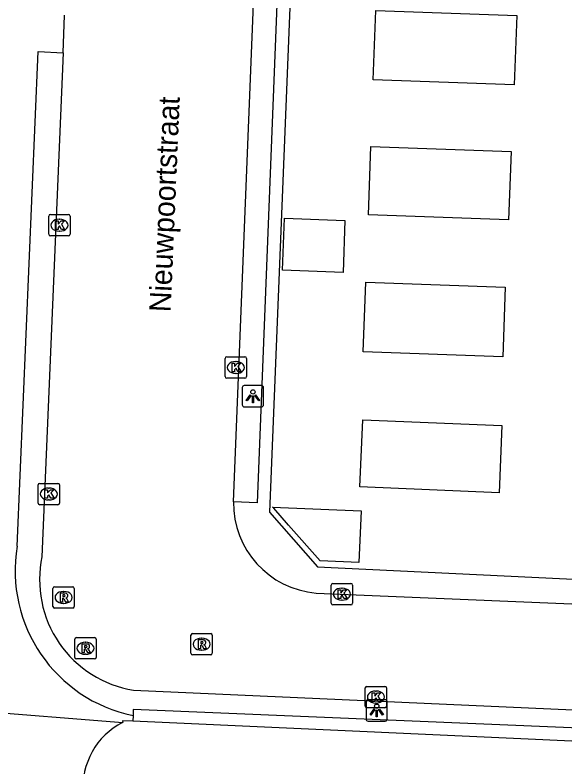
# Model space of a CAD drawing. Extents: x 160732 to 162105, y 387428 to 388479.
# Drawn here: x 161104.81 to 161130.59, y 387524.95 to 387560.21 of the extents above; entities that cross this region are included whole.
import ezdxf

# ---------------------------------------------------------------- set-up
doc = ezdxf.new("R2010")
doc.units = 0
for name, color, linetype in [('IMGEO_Kolk', 7, 'Continuous'), ('IMGEO_Lichtpunt', 7, 'Continuous'), ('IMGEO_Openbare_ruimte_label', 7, 'Continuous'), ('IMGEO_Pand', 7, 'Continuous'), ('IMGEO_Rijbaan_lokaal_open', 7, 'Continuous'), ('IMGEO_Rioolput', 7, 'Continuous'), ('IMGEO_Voetpad_open', 7, 'Continuous')]:
    doc.layers.add(name, color=color, linetype=linetype)

msp = doc.modelspace()

# ---------------------------------------------------------------- linework, layer by layer
at = {"layer": 'IMGEO_Kolk'}
for p, q in [((161106.393, 387549.931), (161106.393, 387550.783)), ((161106.468, 387550.857), (161107.32, 387550.857)), ((161106.881, 387550.637), (161106.906, 387550.637)), ((161107.394, 387550.783), (161107.394, 387549.931)), ((161106.904, 387550.077), (161106.879, 387550.077)), ((161107.32, 387549.857), (161106.468, 387549.857)), ((161114.664, 387543.255), (161114.664, 387544.107)), ((161114.739, 387544.181), (161115.591, 387544.181)), ((161115.152, 387543.961), (161115.177, 387543.961)), ((161115.665, 387544.107), (161115.665, 387543.255)), ((161115.175, 387543.401), (161115.15, 387543.401)), ((161115.591, 387543.181), (161114.739, 387543.181)), ((161105.895, 387537.323), (161105.895, 387538.175)), ((161105.97, 387538.249), (161106.822, 387538.249)), ((161106.383, 387538.029), (161106.408, 387538.029)), ((161106.896, 387538.175), (161106.896, 387537.323)), ((161106.822, 387537.249), (161105.97, 387537.249)), ((161106.406, 387537.469), (161106.381, 387537.469)), ((161119.636, 387532.626), (161119.636, 387533.478)), ((161119.711, 387533.552), (161120.563, 387533.552)), ((161120.124, 387533.332), (161120.149, 387533.332)), ((161120.637, 387533.478), (161120.637, 387532.626)), ((161120.147, 387532.772), (161120.122, 387532.772)), ((161120.563, 387532.552), (161119.711, 387532.552)), ((161121.23, 387527.8), (161121.23, 387528.652)), ((161121.305, 387528.726), (161122.157, 387528.726)), ((161121.718, 387528.506), (161121.743, 387528.506)), ((161122.231, 387528.652), (161122.231, 387527.8)), ((161122.157, 387527.726), (161121.305, 387527.726)), ((161121.741, 387527.946), (161121.716, 387527.946))]:
    msp.add_line(p, q, dxfattribs=at)
for points in [[(161106.393, 387549.931), (161106.393, 387550.783)], [(161106.468, 387550.857), (161107.32, 387550.857)], [(161107.394, 387550.783), (161107.394, 387549.931)], [(161106.714, 387550.557), (161106.837, 387550.557), (161106.837, 387550.406), (161106.967, 387550.557), (161107.131, 387550.557), (161106.985, 387550.406), (161107.138, 387550.157), (161106.986, 387550.157), (161106.901, 387550.321), (161106.837, 387550.254), (161106.837, 387550.157), (161106.714, 387550.157), (161106.714, 387550.557)], [(161107.32, 387549.857), (161106.468, 387549.857)], [(161114.664, 387543.255), (161114.664, 387544.107)], [(161114.739, 387544.181), (161115.591, 387544.181)], [(161115.665, 387544.107), (161115.665, 387543.255)], [(161114.985, 387543.881), (161115.108, 387543.881), (161115.108, 387543.73), (161115.238, 387543.881), (161115.402, 387543.881), (161115.256, 387543.73), (161115.409, 387543.481), (161115.257, 387543.481), (161115.172, 387543.645), (161115.108, 387543.578), (161115.108, 387543.481), (161114.985, 387543.481), (161114.985, 387543.881)], [(161115.591, 387543.181), (161114.739, 387543.181)], [(161105.895, 387537.323), (161105.895, 387538.175)], [(161105.97, 387538.249), (161106.822, 387538.249)], [(161106.216, 387537.949), (161106.339, 387537.949), (161106.339, 387537.798), (161106.469, 387537.949), (161106.633, 387537.949), (161106.487, 387537.798), (161106.64, 387537.549), (161106.488, 387537.549), (161106.403, 387537.713), (161106.339, 387537.646), (161106.339, 387537.549), (161106.216, 387537.549), (161106.216, 387537.949)], [(161106.896, 387538.175), (161106.896, 387537.323)], [(161106.822, 387537.249), (161105.97, 387537.249)], [(161119.636, 387532.626), (161119.636, 387533.478)], [(161119.711, 387533.552), (161120.563, 387533.552)], [(161120.637, 387533.478), (161120.637, 387532.626)], [(161119.957, 387533.252), (161120.08, 387533.252), (161120.08, 387533.101), (161120.21, 387533.252), (161120.374, 387533.252), (161120.228, 387533.101), (161120.381, 387532.852), (161120.229, 387532.852), (161120.144, 387533.016), (161120.08, 387532.949), (161120.08, 387532.852), (161119.957, 387532.852), (161119.957, 387533.252)], [(161120.563, 387532.552), (161119.711, 387532.552)], [(161121.23, 387527.8), (161121.23, 387528.652)], [(161121.305, 387528.726), (161122.157, 387528.726)], [(161121.551, 387528.426), (161121.674, 387528.426), (161121.674, 387528.275), (161121.804, 387528.426), (161121.968, 387528.426), (161121.822, 387528.275), (161121.975, 387528.026), (161121.823, 387528.026), (161121.738, 387528.19), (161121.674, 387528.123), (161121.674, 387528.026), (161121.551, 387528.026), (161121.551, 387528.426)], [(161122.231, 387528.652), (161122.231, 387527.8)], [(161122.157, 387527.726), (161121.305, 387527.726)]]:
    msp.add_lwpolyline(points, dxfattribs=at)
for centre, start, end in [((161106.47, 387550.781), 91.552, 178.448), ((161106.47, 387550.781), 91.552, 178.448), ((161107.318, 387550.781), 1.552, 88.448), ((161107.318, 387550.781), 1.552, 88.448), ((161106.47, 387549.933), 181.552, 268.448), ((161106.47, 387549.933), 181.552, 268.448), ((161107.318, 387549.933), 271.552, 358.448), ((161107.318, 387549.933), 271.552, 358.448), ((161114.741, 387544.105), 91.552, 178.448), ((161114.741, 387544.105), 91.552, 178.448), ((161115.589, 387544.105), 1.552, 88.448), ((161115.589, 387544.105), 1.552, 88.448), ((161114.741, 387543.257), 181.552, 268.448), ((161114.741, 387543.257), 181.552, 268.448), ((161115.589, 387543.257), 271.552, 358.448), ((161115.589, 387543.257), 271.552, 358.448), ((161105.972, 387538.173), 91.552, 178.448), ((161105.972, 387538.173), 91.552, 178.448), ((161106.82, 387538.173), 1.552, 88.448), ((161106.82, 387538.173), 1.552, 88.448), ((161105.972, 387537.325), 181.552, 268.448), ((161105.972, 387537.325), 181.552, 268.448), ((161106.82, 387537.325), 271.552, 358.448), ((161106.82, 387537.325), 271.552, 358.448), ((161119.713, 387533.476), 91.552, 178.448), ((161119.713, 387533.476), 91.552, 178.448), ((161120.561, 387533.476), 1.552, 88.448), ((161120.561, 387533.476), 1.552, 88.448), ((161119.713, 387532.628), 181.552, 268.448), ((161119.713, 387532.628), 181.552, 268.448), ((161120.561, 387532.628), 271.552, 358.448), ((161120.561, 387532.628), 271.552, 358.448), ((161121.307, 387528.65), 91.552, 178.448), ((161121.307, 387528.65), 91.552, 178.448), ((161122.155, 387528.65), 1.552, 88.448), ((161122.155, 387528.65), 1.552, 88.448), ((161121.307, 387527.802), 181.552, 268.448), ((161121.307, 387527.802), 181.552, 268.448), ((161122.155, 387527.802), 271.552, 358.448), ((161122.155, 387527.802), 271.552, 358.448)]:
    msp.add_arc(centre, 0.0765, start, end, dxfattribs=at)
for centre, major_axis, ratio, start_param, end_param in [((161106.88, 387550.357), (-0.387, 0.002), 0.722429, 4.712389, 7.853982), ((161106.905, 387550.357), (-0.39, 0.002), 0.717154, 1.570796, 4.712389), ((161115.151, 387543.681), (-0.387, 0.002), 0.722429, 4.712389, 7.853982), ((161115.176, 387543.681), (-0.39, 0.002), 0.717154, 1.570796, 4.712389), ((161106.382, 387537.749), (-0.387, 0.002), 0.722429, 4.712389, 7.853982), ((161106.407, 387537.749), (-0.39, 0.002), 0.717154, 1.570796, 4.712389), ((161120.123, 387533.052), (-0.387, 0.002), 0.722429, 4.712389, 7.853982), ((161120.148, 387533.052), (-0.39, 0.002), 0.717154, 1.570796, 4.712389), ((161121.717, 387528.226), (-0.387, 0.002), 0.722429, 4.712389, 7.853982), ((161121.742, 387528.226), (-0.39, 0.002), 0.717154, 1.570796, 4.712389)]:
    msp.add_ellipse(centre, major_axis=major_axis, ratio=ratio, start_param=start_param, end_param=end_param, dxfattribs=at)
at = {"layer": 'IMGEO_Lichtpunt'}
for p, q in [((161115.466, 387542.738), (161115.466, 387541.931)), ((161115.466, 387542.738), (161115.466, 387541.931)), ((161116.368, 387542.833), (161115.56, 387542.833)), ((161116.368, 387542.833), (161115.56, 387542.833)), ((161116.462, 387541.931), (161116.462, 387542.738)), ((161116.462, 387541.931), (161116.462, 387542.738)), ((161115.56, 387541.837), (161116.368, 387541.837)), ((161115.56, 387541.837), (161116.368, 387541.837)), ((161122.172, 387528.098), (161121.364, 387528.098)), ((161122.172, 387528.098), (161121.364, 387528.098)), ((161121.27, 387528.003), (161121.27, 387527.196)), ((161121.27, 387528.003), (161121.27, 387527.196)), ((161122.266, 387527.196), (161122.266, 387528.003)), ((161122.266, 387527.196), (161122.266, 387528.003)), ((161121.364, 387527.102), (161122.172, 387527.102)), ((161121.364, 387527.102), (161122.172, 387527.102))]:
    msp.add_line(p, q, dxfattribs=at)
for points in [[(161115.84, 387542.402), (161115.879, 387542.374), (161115.691, 387542.112), (161115.653, 387542.139), (161115.84, 387542.402)], [(161115.942, 387542.354), (161115.989, 387542.354), (161115.989, 387542.032), (161115.942, 387542.032), (161115.942, 387542.354)], [(161116.052, 387542.374), (161116.09, 387542.401), (161116.277, 387542.139), (161116.238, 387542.111), (161116.052, 387542.374)], [(161121.644, 387527.667), (161121.683, 387527.639), (161121.495, 387527.377), (161121.457, 387527.404), (161121.644, 387527.667)], [(161121.746, 387527.619), (161121.793, 387527.619), (161121.793, 387527.297), (161121.746, 387527.297), (161121.746, 387527.619)], [(161121.856, 387527.639), (161121.894, 387527.666), (161122.081, 387527.404), (161122.042, 387527.376), (161121.856, 387527.639)]]:
    msp.add_lwpolyline(points, dxfattribs=at)
for centre in [(161115.965, 387542.536), (161121.769, 387527.801)]:
    msp.add_circle(centre, 0.0994, dxfattribs=at)
for centre, start, end in [((161115.56, 387542.738), 90, 180), ((161115.56, 387542.738), 90, 180), ((161116.368, 387542.738), 0, 90), ((161116.368, 387542.738), 0, 90), ((161115.56, 387541.931), 180, 270), ((161115.56, 387541.931), 180, 270), ((161116.368, 387541.931), 270, 0), ((161116.368, 387541.931), 270, 360), ((161121.364, 387528.003), 90, 180), ((161121.364, 387528.003), 90, 180), ((161122.172, 387528.003), 0, 90), ((161122.172, 387528.003), 0, 90), ((161121.364, 387527.196), 180, 270), ((161121.364, 387527.196), 180, 270), ((161122.172, 387527.196), 270, 0), ((161122.172, 387527.196), 270, 360)]:
    msp.add_arc(centre, 0.0946, start, end, dxfattribs=at)
at = {"layer": 'IMGEO_Pand'}
for points in [[(161128.331, 387560.19), (161128.215, 387556.943), (161121.61, 387557.179), (161121.726, 387560.426), (161128.331, 387560.19)], [(161128.068, 387553.807), (161127.953, 387550.605), (161121.386, 387550.839), (161121.501, 387554.041), (161128.068, 387553.807)], [(161117.358, 387548.243), (161117.444, 387550.679), (161120.277, 387550.578), (161120.19, 387548.142), (161117.358, 387548.243)], [(161127.794, 387547.443), (161127.678, 387544.183), (161121.141, 387544.417), (161121.257, 387547.676), (161127.794, 387547.443)], [(161127.642, 387540.955), (161127.511, 387537.81), (161120.983, 387538.082), (161121.114, 387541.227), (161127.642, 387540.955)], [(161121.037, 387536.966), (161120.936, 387534.537), (161119.112, 387534.613), (161117.632, 387536.295), (161116.94, 387537.082), (161116.89, 387537.139), (161121.037, 387536.966)]]:
    msp.add_lwpolyline(points, dxfattribs=at)
at = {"layer": 'IMGEO_Rijbaan_lokaal_open'}
for points in [[(161115.055, 387537.387), (161116.968, 387584.894), (161117.052, 387588.641)], [(161107.063, 387558.443), (161107.126, 387560.211)], [(161107.063, 387558.443), (161106.074, 387534.809)], [(161118.93, 387533.102), (161150.782, 387531.772)], [(161110.371, 387528.545), (161147.402, 387526.893)]]:
    msp.add_lwpolyline(points, dxfattribs=at)
for centre, radius, start, end in [((161119.292, 387537.324), 4.238, 179.1513, 265.0959), ((161111.214, 387533.729), 5.252, 168.1366, 260.7623)]:
    msp.add_arc(centre, radius, start, end, dxfattribs=at)
at = {"layer": 'IMGEO_Rioolput'}
for p, q in [((161106.587, 387532.472), (161106.587, 387533.324)), ((161106.662, 387533.398), (161107.514, 387533.398)), ((161107.588, 387533.324), (161107.588, 387532.472)), ((161107.075, 387533.178), (161107.1, 387533.178)), ((161107.098, 387532.618), (161107.073, 387532.618)), ((161107.514, 387532.398), (161106.662, 387532.398)), ((161113.134, 387531.205), (161113.986, 387531.205)), ((161107.613, 387530.088), (161107.613, 387530.94)), ((161107.688, 387531.014), (161108.54, 387531.014)), ((161108.614, 387530.94), (161108.614, 387530.088)), ((161113.059, 387530.279), (161113.059, 387531.131)), ((161113.547, 387530.985), (161113.572, 387530.985)), ((161114.06, 387531.131), (161114.06, 387530.279)), ((161108.101, 387530.794), (161108.126, 387530.794)), ((161108.124, 387530.234), (161108.099, 387530.234)), ((161113.986, 387530.205), (161113.134, 387530.205)), ((161113.57, 387530.425), (161113.545, 387530.425)), ((161108.54, 387530.014), (161107.688, 387530.014))]:
    msp.add_line(p, q, dxfattribs=at)
for points in [[(161106.587, 387532.472), (161106.587, 387533.324)], [(161106.662, 387533.398), (161107.514, 387533.398)], [(161107.588, 387533.324), (161107.588, 387532.472)], [(161107.176, 387533.096), (161106.924, 387533.098), (161106.924, 387532.698)], [(161107.102, 387533.017), (161107.048, 387533.017), (161107.048, 387532.936)], [(161106.924, 387532.698), (161107.048, 387532.698), (161107.048, 387532.86), (161107.059, 387532.86)], [(161107.048, 387532.936), (161107.1, 387532.936)], [(161107.106, 387532.831), (161107.177, 387532.698), (161107.317, 387532.698), (161107.252, 387532.824)], [(161107.514, 387532.398), (161106.662, 387532.398)], [(161113.134, 387531.205), (161113.986, 387531.205)], [(161107.613, 387530.088), (161107.613, 387530.94)], [(161107.688, 387531.014), (161108.54, 387531.014)], [(161108.614, 387530.94), (161108.614, 387530.088)], [(161113.059, 387530.279), (161113.059, 387531.131)], [(161113.648, 387530.903), (161113.396, 387530.905), (161113.396, 387530.505)], [(161114.06, 387531.131), (161114.06, 387530.279)], [(161108.202, 387530.712), (161107.95, 387530.714), (161107.95, 387530.314)], [(161108.128, 387530.633), (161108.074, 387530.633), (161108.074, 387530.552)], [(161108.074, 387530.552), (161108.126, 387530.552)], [(161113.396, 387530.505), (161113.52, 387530.505), (161113.52, 387530.667), (161113.531, 387530.667)], [(161113.574, 387530.824), (161113.52, 387530.824), (161113.52, 387530.743)], [(161113.52, 387530.743), (161113.572, 387530.743)], [(161113.578, 387530.638), (161113.649, 387530.505), (161113.789, 387530.505), (161113.724, 387530.631)], [(161107.95, 387530.314), (161108.074, 387530.314), (161108.074, 387530.476), (161108.085, 387530.476)], [(161108.132, 387530.447), (161108.203, 387530.314), (161108.343, 387530.314), (161108.278, 387530.44)], [(161113.986, 387530.205), (161113.134, 387530.205)], [(161108.54, 387530.014), (161107.688, 387530.014)]]:
    msp.add_lwpolyline(points, dxfattribs=at)
for centre, radius, start, end in [((161106.664, 387533.322), 0.0765, 91.552, 178.448), ((161106.664, 387533.322), 0.0765, 91.552, 178.448), ((161107.512, 387533.322), 0.0765, 1.552, 88.448), ((161107.512, 387533.322), 0.0765, 1.552, 88.448), ((161107.108, 387532.921), 0.0964, 77.0061, 93.1865), ((161107.122, 387532.978), 0.0378, 276.6634, 79.6772), ((161107.175, 387532.986), 0.109, 350.3612, 89.416), ((161107.173, 387532.986), 0.112, 277.5842, 350.9817), ((161107.058, 387532.807), 0.0533, 26.0293, 88.6989), ((161107.084, 387533.125), 0.19, 274.7715, 282.9687), ((161107.157, 387532.771), 0.108, 29.5134, 73.7905), ((161106.664, 387532.474), 0.0765, 181.552, 268.448), ((161106.664, 387532.474), 0.0765, 181.552, 268.448), ((161107.512, 387532.474), 0.0765, 271.552, 358.448), ((161107.512, 387532.474), 0.0765, 271.552, 358.448), ((161113.136, 387531.129), 0.0765, 91.552, 178.448), ((161113.136, 387531.129), 0.0765, 91.552, 178.448), ((161113.984, 387531.129), 0.0765, 1.552, 88.448), ((161113.984, 387531.129), 0.0765, 1.552, 88.448), ((161107.69, 387530.938), 0.0765, 91.552, 178.448), ((161107.69, 387530.938), 0.0765, 91.552, 178.448), ((161108.538, 387530.938), 0.0765, 1.552, 88.448), ((161108.538, 387530.938), 0.0765, 1.552, 88.448), ((161113.647, 387530.793), 0.109, 350.3612, 89.416), ((161108.11, 387530.741), 0.19, 274.7715, 282.9687), ((161108.134, 387530.537), 0.0964, 77.0061, 93.1865), ((161108.148, 387530.594), 0.0378, 276.6634, 79.6772), ((161108.201, 387530.602), 0.109, 350.3612, 89.416), ((161108.199, 387530.602), 0.112, 277.5842, 350.9817), ((161113.53, 387530.614), 0.0533, 26.0293, 88.6989), ((161113.556, 387530.932), 0.19, 274.7715, 282.9687), ((161113.58, 387530.728), 0.0964, 77.0061, 93.1865), ((161113.594, 387530.785), 0.0378, 276.6634, 79.6772), ((161113.645, 387530.793), 0.112, 277.5842, 350.9817), ((161113.629, 387530.578), 0.108, 29.5134, 73.7905), ((161108.084, 387530.423), 0.0533, 26.0293, 88.6989), ((161108.183, 387530.387), 0.108, 29.5134, 73.7905), ((161113.136, 387530.281), 0.0765, 181.552, 268.448), ((161113.136, 387530.281), 0.0765, 181.552, 268.448), ((161113.984, 387530.281), 0.0765, 271.552, 358.448), ((161113.984, 387530.281), 0.0765, 271.552, 358.448), ((161107.69, 387530.09), 0.0765, 181.552, 268.448), ((161107.69, 387530.09), 0.0765, 181.552, 268.448), ((161108.538, 387530.09), 0.0765, 271.552, 358.448), ((161108.538, 387530.09), 0.0765, 271.552, 358.448)]:
    msp.add_arc(centre, radius, start, end, dxfattribs=at)
for centre, major_axis, ratio, start_param, end_param in [((161107.074, 387532.898), (-0.387, 0.002), 0.722429, 4.712389, 7.853982), ((161107.099, 387532.898), (-0.39, 0.002), 0.717154, 1.570796, 4.712389), ((161113.546, 387530.705), (-0.387, 0.002), 0.722429, 4.712389, 7.853982), ((161113.571, 387530.705), (-0.39, 0.002), 0.717154, 1.570796, 4.712389), ((161108.1, 387530.514), (-0.387, 0.002), 0.722429, 4.712389, 7.853982), ((161108.125, 387530.514), (-0.39, 0.002), 0.717154, 1.570796, 4.712389)]:
    msp.add_ellipse(centre, major_axis=major_axis, ratio=ratio, start_param=start_param, end_param=end_param, dxfattribs=at)
at = {"layer": 'IMGEO_Voetpad_open'}
for points in [[(161118.188, 387588.85), (161116.164, 387537.336), (161115.055, 387537.387)], [(161118.779, 387585.972), (161118.175, 387572.62), (161116.748, 387536.89), (161118.993, 387534.338), (161131.639, 387533.72), (161136.177, 387533.542), (161136.191, 387533.922)], [(161104.915, 387535.3), (161105.903, 387558.494), (161107.063, 387558.443)], [(161102.795, 387527.593), (161109.858, 387527.034)], [(161110.347, 387527.357), (161110.336, 387527.095)], [(161147.402, 387526.893), (161147.335, 387526.094), (161110.352, 387527.649), (161110.347, 387527.357)], [(161110.336, 387527.095), (161109.847, 387527.117), (161109.858, 387527.034)], [(161149.102, 387525.337), (161110.336, 387527.095)]]:
    msp.add_lwpolyline(points, dxfattribs=at)
for centre, radius, start, end in [((161111.745, 387534.142), 6.927, 170.3752, 258.3591), ((161111.376, 387524.019), 3.376, 116.733, 185.0668)]:
    msp.add_arc(centre, radius, start, end, dxfattribs=at)

# ---------------------------------------------------------------- texts
at = {"layer": 'IMGEO_Openbare_ruimte_label'}
msp.add_text('Nieuwpoortstraat', height=1, rotation=87.5353, dxfattribs=at).set_placement((161112.102, 387546.263))

doc.saveas('drawing.dxf')
